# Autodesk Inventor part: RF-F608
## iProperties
Created: 2009-01
Part Number: RF-F608
Material: ---
Document SubType Name: Blech
Designer: R.Schröder
Surface Area: 5.66315 cm^2
Volume: 0.189002 cm^3
Description: Flachsteckhülse
Manager: Dr.-Ing. Roland Schröder
Company: Das Entwicklungsbüro
Category: Katalog
__ICENTER__: VpEWjrdpDpK1mcsYxBHpAaD71i0vtZxVcjkZAQreTbwLsZ5bQ8DTdzysRKY9+fwCKq8Zb+NPj5nSj+XJiLbxNBDsXn/Fw28QeCEHmubG234lFGBly/wj7EwNsOPmX2hh+juTl9kZkHe3CHk9SxMId8zaBBP6Au1q
__ICENTER_VERSION__: 4.0.10
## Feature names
1. Verriegelungsbuckel [Extrusion]
2. Heckansatz [Extrusion]
3. Klemmschale [Extrusion]
4. Erhebung1
5. Klemmflügel [Extrusion]
6. Farbrhülse [Extrusion]
7. Grobblech1
8. Biegung1
